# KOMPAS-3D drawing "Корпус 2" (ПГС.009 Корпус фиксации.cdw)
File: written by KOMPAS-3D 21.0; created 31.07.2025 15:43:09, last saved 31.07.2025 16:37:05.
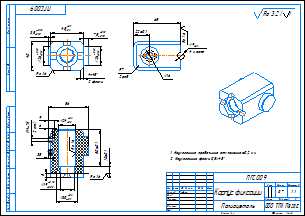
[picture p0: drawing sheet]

Sheet 1: A4x2, landscape

Document properties: Полное имя файла: C:\Users\User\Desktop\ПЕРСПЕКТИВА кд\Чертежи\ПГС.009 Корпус фиксации.cdw; Автор: User; Знак неуказанной шероховатости: 4; Параметр неуказанной шероховатости: Ra 3.2; Масса: 0.699666; Форматы листов документа: A4@4~2

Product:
- Part/product: Корпус 2
    Масса: 0.699666
    Форматы листов документа: A4@4~2
  - Body: Тело 1
      Масса: 0.703675
  - Body: Тело 3
      Масса: 0.703675

Title block, sheet 1: Наименование: Корпус фиксации; designation: ПГС.009; Материал: Полиацеталь; Масса: 0,7; Количество листов документа: 1; organisation: ООО ТПК Пегас; Форматы листов документа: A4 2; stored path: C:\Users\User\Desktop\ПЕРСПЕКТИВА кд\Чертежи\ПГС.010 Корпус фиксации.cdw; Разработал: Гайсин

Views: Вид 1, Спереди, Проекционный вид 2, Местный разрез 1, Проекционный вид 3, Вид 4, Изометрия
Referenced files in C:\Users\User\Desktop\ПЕРСПЕКТИВА кд\Модель\: ПГС.009 Корпус фиксации.m3d
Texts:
  Ra 1.6
  Корпус 2
  Ra 3.2
  Ra 3.2 ( )
Dimensions and other numbers on the sheet: 40; 45; 26; 3,5; 7,5; 4; 2 фаски; 56; 24; 50±0,1; 10±0,1; 6; 9; -7Н; 2 отв; 30; 5; 19; 65; 16; 7; 2 рад; 4 места; 22±0,1; 1:1; 1; 0,7

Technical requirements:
  Неуказанные предельные отклонения  0,2 мм
  Неуказанные фаски 0,5х45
